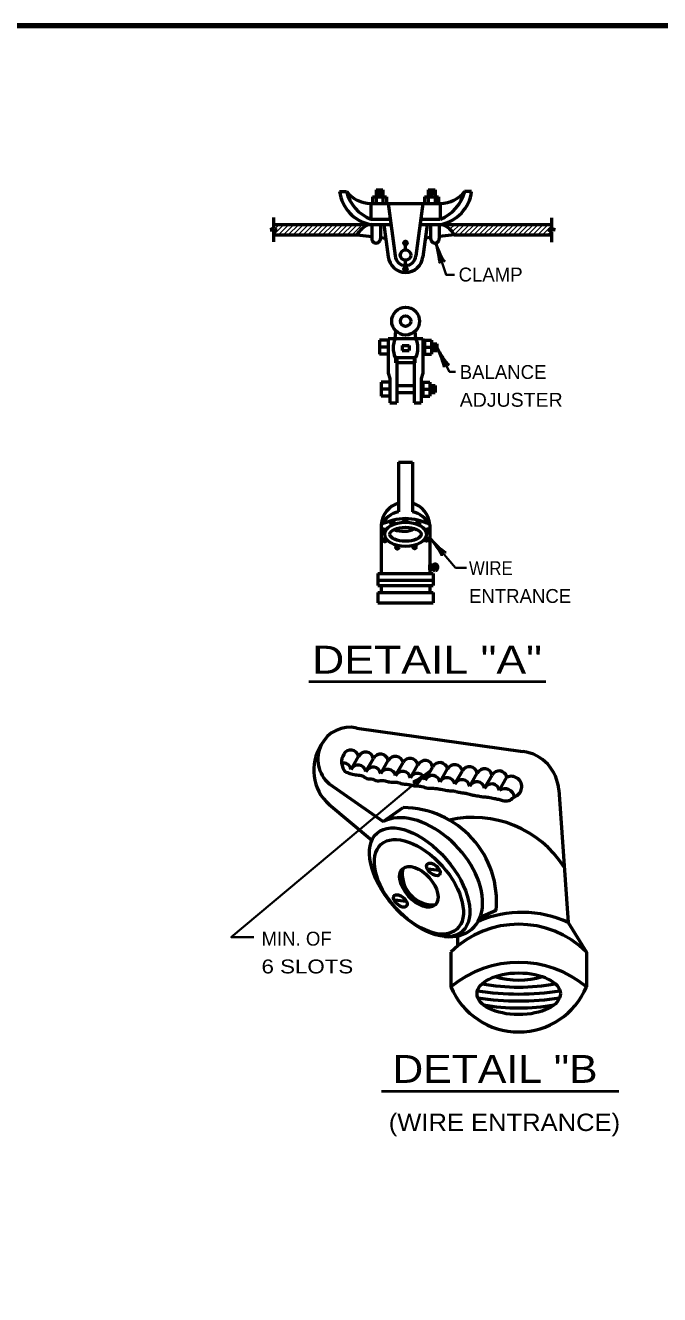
# Model space of a CAD drawing. Extents: x -370 to 486, y -203 to 341.
# Drawn here: x -153.5 to -43.9, y 115.9 to 334.9 of the extents above; entities that cross this region are included whole.
import ezdxf
from ezdxf.enums import TextEntityAlignment as Align

# ---------------------------------------------------------------- set-up
doc = ezdxf.new("R2010")
doc.units = 0
doc.header["$LTSCALE"] = 0.96
doc.layers.add('1', color=7, linetype='Continuous', lineweight=53)

msp = doc.modelspace()

# ---------------------------------------------------------------- hatches: boundary and pattern name
at = {"layer": '1'}
for points in [[(-87.5088, 249.4967, 1), (-88.1088, 249.4967, 1)], [(-91.2993, 247.743, 1), (-91.8993, 247.743, 1)], [(-89.7594, 249.0701, 1), (-90.3594, 249.0701, 1)], [(-85.2937, 249.0938, 1), (-85.8937, 249.0938, 1)], [(-83.7302, 247.743, 1), (-84.3302, 247.743, 1)], [(-91.086, 246.096, 1), (-91.686, 246.096, 1)], [(-83.8723, 246.1908, 1), (-84.4723, 246.1908, 1)], [(-88.9065, 244.84, 1), (-89.5065, 244.84, 1)], [(-85.9215, 244.8993, 1), (-86.5215, 244.8993, 1)]]:
    msp.add_hatch(color=256, dxfattribs=at).paths.add_polyline_path(points)
h = msp.add_hatch(color=256, dxfattribs=at)
edge = h.paths.add_edge_path()
edge.add_ellipse((-82.7123, 241.4022), major_axis=(0, -0.6), ratio=0.75, start_angle=0, end_angle=360)

# ---------------------------------------------------------------- linework, layer by layer
for p, q in [((-99.2043, 306.2737), (-98.0043, 306.2737)), ((-93.5043, 305.3737), (-91.1044, 305.3737)), ((-93.5043, 305.3737), (-93.5043, 304.1737)), ((-92.9043, 306.5737), (-92.9043, 304.1737)), ((-92.9043, 306.5737), (-91.7044, 306.5737)), ((-92.9043, 305.9737), (-91.7044, 305.9737)), ((-92.6043, 306.2737), (-92.0044, 306.2737)), ((-92.6043, 305.6737), (-92.0044, 305.6737)), ((-91.7044, 306.5737), (-91.7044, 304.1737)), ((-91.1044, 305.3737), (-91.1044, 304.1737)), ((-84.5042, 305.3737), (-82.1043, 305.3737)), ((-84.5042, 305.3737), (-84.5042, 304.1737)), ((-83.9042, 306.5737), (-83.9042, 304.1737)), ((-83.9042, 306.5737), (-82.7043, 306.5737)), ((-83.9042, 305.9737), (-82.7043, 305.9737)), ((-83.6042, 306.2737), (-83.0043, 306.2737)), ((-83.6042, 305.6737), (-83.0043, 305.6737)), ((-82.7043, 306.5737), (-82.7043, 304.1737)), ((-82.1043, 305.3737), (-82.1043, 304.1737)), ((-76.4043, 306.2737), (-77.6043, 306.2737)), ((-93.8043, 304.1737), (-93.8043, 301.4737)), ((-90.8044, 304.1737), (-89.6043, 295.1727)), ((-84.8042, 304.1737), (-86.0043, 295.1727)), ((-81.8043, 304.1737), (-81.8043, 301.4737)), ((-110.6043, 301.7737), (-110.6043, 299.9737)), ((-110.6043, 300.5737), (-93.8043, 300.5737)), ((-93.6351, 300.5737), (-94.2328, 300.5214)), ((-93.8043, 301.4737), (-90.4444, 301.4737)), ((-93.8043, 300.5737), (-90.3244, 300.5737)), ((-93.6351, 300.5737), (-93.6351, 298.1737)), ((-92.1351, 300.5737), (-92.1351, 298.1737)), ((-91.5351, 300.5737), (-90.7938, 295.0142)), ((-85.2842, 300.5737), (-81.8043, 300.5737)), ((-85.1642, 301.4737), (-81.8043, 301.4737)), ((-84.0738, 300.5737), (-84.8149, 295.0142)), ((-83.4738, 300.5737), (-83.4738, 298.1737)), ((-81.9738, 300.5737), (-81.9738, 298.1737)), ((-81.9697, 300.5737), (-81.372, 300.5214)), ((-81.8043, 300.5737), (-62.6043, 300.5737)), ((-62.5683, 301.7295), (-62.5683, 299.9295)), ((-110.6043, 299.9737), (-111.2043, 299.6737)), ((-111.2043, 299.6737), (-110.0043, 299.6737)), ((-110.0043, 299.6737), (-110.6043, 299.3737)), ((-110.6043, 299.3737), (-110.6043, 297.5737)), ((-110.6043, 298.7737), (-96.2043, 298.7737)), ((-96.2043, 298.7737), (-93.6351, 298.4754)), ((-92.1351, 298.3013), (-91.2179, 298.1948)), ((-83.4738, 298.3012), (-84.3909, 298.1948)), ((-79.4043, 298.7737), (-81.9738, 298.4754)), ((-79.4043, 298.7737), (-62.6043, 298.7737)), ((-61.9683, 299.6295), (-63.1683, 299.6295)), ((-63.1683, 299.6295), (-62.5683, 299.3295)), ((-62.5683, 299.9295), (-61.9683, 299.6295)), ((-62.5683, 299.3295), (-62.5683, 297.5295)), ((-87.8043, 296.1949), (-87.8043, 297.0805)), ((-87.8043, 293.1956), (-87.8043, 294.3949)), ((-90.8043, 280.5938), (-92.3043, 280.5938)), ((-92.3043, 280.5938), (-92.3043, 278.1938)), ((-90.8043, 280.8938), (-84.8043, 280.8938)), ((-90.8043, 280.8938), (-90.8043, 274.8938)), ((-89.6043, 280.8938), (-89.491, 282.1892)), ((-86.0043, 280.8938), (-86.1167, 282.1779)), ((-84.8043, 280.8938), (-84.8043, 274.8938)), ((-84.8043, 280.5938), (-83.3043, 280.5938)), ((-84.5043, 280.5938), (-84.5043, 278.1938)), ((-83.3043, 280.5938), (-83.3043, 278.1938)), ((-90.8043, 279.3938), (-92.3043, 279.3938)), ((-88.4043, 279.6938), (-87.2043, 279.6938)), ((-88.4043, 279.6938), (-88.4043, 278.7938)), ((-88.4043, 278.7938), (-87.2043, 278.7938)), ((-87.2043, 279.6938), (-87.2043, 278.7938)), ((-84.5043, 279.3938), (-83.3043, 279.3938)), ((-83.3043, 279.9938), (-82.4043, 279.9938)), ((-83.3043, 278.7938), (-82.4043, 278.7938)), ((-83.0793, 279.6938), (-83.0793, 279.0938)), ((-82.8543, 279.9938), (-82.8543, 278.7938)), ((-82.6293, 279.6938), (-82.6293, 279.0938)), ((-82.4043, 279.9938), (-82.4043, 278.7938)), ((-90.8043, 278.1938), (-92.3043, 278.1938)), ((-89.6043, 277.5938), (-86.0043, 277.5938)), ((-89.4543, 276.6938), (-89.4543, 277.5938)), ((-89.4543, 276.7655), (-86.1543, 276.7655)), ((-89.3919, 276.6938), (-89.3919, 277.5938)), ((-89.3919, 276.6938), (-89.3919, 277.5938)), ((-89.3644, 276.6938), (-89.3644, 277.5938)), ((-89.3644, 276.6938), (-89.3644, 277.5938)), ((-89.3095, 276.6938), (-89.3095, 277.5938)), ((-89.3043, 277.5938), (-89.3043, 269.7938)), ((-86.3043, 277.5938), (-86.3043, 269.7938)), ((-86.2472, 276.6938), (-86.2472, 277.5938)), ((-86.2334, 276.6938), (-86.2334, 277.5938)), ((-86.206, 276.6938), (-86.206, 277.5938)), ((-86.1922, 276.6938), (-86.1922, 277.5938)), ((-86.1785, 276.6938), (-86.1785, 277.5938)), ((-86.1543, 276.6938), (-86.1543, 277.5938)), ((-84.8043, 278.1938), (-83.3043, 278.1938)), ((-90.8043, 274.8938), (-90.5043, 273.9938)), ((-90.5043, 273.9938), (-90.5043, 269.7938)), ((-84.8043, 274.8938), (-85.1043, 273.9938)), ((-85.1043, 273.9938), (-85.1043, 269.7938)), ((-90.5387, 273.3522), (-92.0387, 273.3522)), ((-92.0387, 273.3522), (-92.0387, 270.9522)), ((-90.5387, 272.1522), (-92.0387, 272.1522)), ((-89.3043, 272.7522), (-86.3043, 272.7522)), ((-85.1043, 273.3522), (-83.6043, 273.3522)), ((-84.8043, 273.3522), (-84.8043, 270.9522)), ((-84.8043, 272.1522), (-83.6043, 272.1522)), ((-83.6043, 273.3522), (-83.6043, 270.9522)), ((-83.6043, 272.7522), (-82.7043, 272.7522)), ((-83.3793, 272.4522), (-83.3793, 271.8522)), ((-83.1543, 272.7522), (-83.1543, 271.5522)), ((-82.9293, 272.4522), (-82.9293, 271.8522)), ((-82.7043, 272.7522), (-82.7043, 271.5522)), ((-90.5387, 270.9522), (-92.0387, 270.9522)), ((-90.5043, 269.7938), (-89.3043, 269.7938)), ((-89.3043, 271.5522), (-86.3043, 271.5522)), ((-86.3043, 269.7938), (-85.1043, 269.7938)), ((-85.1043, 270.9522), (-83.6043, 270.9522)), ((-83.6043, 271.5522), (-82.7043, 271.5522)), ((-89.0043, 259.5522), (-86.6043, 259.5522)), ((-89.0043, 259.5522), (-89.0043, 251.0022)), ((-86.6043, 259.5522), (-86.6043, 251.0022)), ((-92.0043, 248.7522), (-92.0043, 240.3522)), ((-83.6043, 248.7522), (-83.6043, 241.8522)), ((-92.6043, 240.3522), (-83.0043, 240.3522)), ((-92.6043, 240.3522), (-92.6043, 238.2522)), ((-92.6043, 239.1522), (-83.0043, 239.1522)), ((-83.6043, 240.9522), (-83.6043, 240.3522)), ((-83.0043, 240.3522), (-83.0043, 238.2522)), ((-92.6043, 238.2522), (-83.0043, 238.2522)), ((-92.6043, 237.0522), (-83.0043, 237.0522)), ((-92.6043, 237.0522), (-92.6043, 235.2522)), ((-92.0043, 238.2522), (-92.0043, 237.0522)), ((-83.6043, 238.2522), (-83.6043, 237.0522)), ((-83.0043, 237.0522), (-83.0043, 235.2522)), ((-92.6043, 235.2522), (-83.0043, 235.2522)), ((-96.2043, 213.6522), (-67.5168, 209.6205)), ((-97.2065, 206.5224), (-95.9123, 208.7641)), ((-94.6433, 206.1622), (-93.3491, 208.4038)), ((-92.08, 205.8019), (-90.7858, 208.0436)), ((-89.5167, 205.4417), (-88.2225, 207.6834)), ((-86.9535, 205.0815), (-85.6594, 207.3231)), ((-84.3902, 204.7212), (-83.096, 206.9629)), ((-81.8269, 204.361), (-80.5327, 206.6026)), ((-79.2637, 204.0007), (-77.9695, 206.2424)), ((-101.0043, 204.0522), (-91.666, 197.5134)), ((-76.7004, 203.6405), (-75.4062, 205.8822)), ((-74.1371, 203.2803), (-72.8429, 205.5219)), ((-71.5739, 202.92), (-70.2796, 205.1617)), ((-61.3364, 202.9927), (-59.734, 180.0792)), ((-101.0043, 200.4522), (-93.6503, 194.2814)), ((-91.666, 197.5134), (-88.2256, 199.9224)), ((-83.9561, 189.3303), (-82.005, 189.1294)), ((-89.6946, 183.9917), (-87.7148, 183.7908)), ((-72.1429, 182.1709), (-74.9313, 180.9801)), ((-78.7546, 176.0669), (-78.7546, 177.7848)), ((-79.9546, 174.9909), (-79.9546, 168.9909))]:
    msp.add_line(p, q, dxfattribs=at)
at = {"layer": '1', "lineweight": 25}
for p, q in [((-110.6043, 298.7737), (-108.8043, 300.5737)), ((-110.5529, 299.6737), (-109.6529, 300.5737)), ((-109.7559, 298.7737), (-107.9559, 300.5737)), ((-108.9073, 298.7737), (-107.1073, 300.5737)), ((-108.0589, 298.7737), (-106.2589, 300.5737)), ((-107.2103, 298.7737), (-105.4103, 300.5737)), ((-106.3617, 298.7737), (-104.5617, 300.5737)), ((-105.5133, 298.7737), (-103.7133, 300.5737)), ((-104.6647, 298.7737), (-102.8647, 300.5737)), ((-103.8161, 298.7737), (-102.0161, 300.5737)), ((-102.9677, 298.7737), (-101.1677, 300.5737)), ((-102.1191, 298.7737), (-100.3191, 300.5737)), ((-101.2707, 298.7737), (-99.4707, 300.5737)), ((-100.4221, 298.7737), (-98.6221, 300.5737)), ((-99.5735, 298.7737), (-97.7735, 300.5737)), ((-98.7251, 298.7737), (-96.9251, 300.5737)), ((-97.8767, 298.7737), (-96.0767, 300.5737)), ((-97.0281, 298.7737), (-95.2281, 300.5737)), ((-80.6056, 300.1182), (-80.1501, 300.5737)), ((-80.1359, 299.7393), (-79.3015, 300.5737)), ((-79.7341, 299.2925), (-78.4529, 300.5737)), ((-79.4043, 298.7737), (-77.6043, 300.5737)), ((-78.5559, 298.7737), (-76.7559, 300.5737)), ((-77.7073, 298.7737), (-75.9073, 300.5737)), ((-76.8589, 298.7737), (-75.0589, 300.5737)), ((-76.0103, 298.7737), (-74.2103, 300.5737)), ((-75.1617, 298.7737), (-73.3617, 300.5737)), ((-74.3133, 298.7737), (-72.5133, 300.5737)), ((-73.4649, 298.7737), (-71.6649, 300.5737)), ((-72.6163, 298.7737), (-70.8163, 300.5737)), ((-71.7679, 298.7737), (-69.9679, 300.5737)), ((-70.9193, 298.7737), (-69.1193, 300.5737)), ((-70.0707, 298.7737), (-68.2707, 300.5737)), ((-69.2223, 298.7737), (-67.4223, 300.5737)), ((-68.3737, 298.7737), (-66.5737, 300.5737)), ((-67.5253, 298.7737), (-65.7253, 300.5737)), ((-66.6767, 298.7737), (-64.8767, 300.5737)), ((-65.8283, 298.7737), (-64.0283, 300.5737)), ((-64.9797, 298.7737), (-63.1797, 300.5737)), ((-64.1311, 298.7737), (-62.5683, 300.3365)), ((-63.2827, 298.7737), (-62.674, 299.3824))]:
    msp.add_line(p, q, dxfattribs=at)
at = {"layer": '1', "lineweight": 40}
for p, q in [((-104.5149, 221.6891), (-63.5509, 221.6891)), ((-91.9537, 150.9917), (-50.9897, 150.9917))]:
    msp.add_line(p, q, dxfattribs=at)
at = {"layer": '1', "lineweight": 158}
msp.add_lwpolyline([(479.406, 334.9398), (-312.294, 334.8398), (-312.194, -191.1602)], dxfattribs=at)
at = {"layer": '1'}
for points in [[(-93.8043, 304.1737), (-90.8044, 304.1737), (-84.8042, 304.1737), (-81.8043, 304.1737)], [(-59.7341, 180.0792), (-56.5546, 174.9909), (-56.5546, 168.9909)]]:
    msp.add_lwpolyline(points, dxfattribs=at)
at = {"layer": '1', "lineweight": 35}
for points in [[(-82.5442, 297.3097), (-80.7948, 291.8891), (-79.3707, 291.8891)], [(-82.2882, 279.2127), (-80.1975, 275.1153), (-79.1584, 275.1153)], [(-83.4318, 246.3099), (-79.1493, 241.3198), (-77.2662, 241.3198)], [(-83.589, 206.2782), (-117.8957, 177.5452), (-114.0022, 177.5452)]]:
    msp.add_lwpolyline(points, dxfattribs=at)
at = {"layer": '1'}
msp.add_lwpolyline([(-83.6043, 240.9522), (-83.6043, 241.8522), (-83.0043, 241.8522), (-83.0043, 240.9522)], close=True, dxfattribs=at)
for centre, radius in [((-87.8035, 295.2949), 0.9), ((-87.8096, 297.3805), 0.3), ((-87.8096, 292.8956), 0.3), ((-87.7981, 283.8904), 2.4), ((-87.7981, 283.8904), 0.9), ((-87.8088, 249.4967), 0.3), ((-91.5993, 247.743), 0.3), ((-90.0594, 249.0701), 0.3), ((-85.5937, 249.0938), 0.3), ((-84.0302, 247.743), 0.3), ((-91.386, 246.096), 0.3), ((-84.1723, 246.1908), 0.3), ((-89.2065, 244.84), 0.3), ((-86.2215, 244.8993), 0.3)]:
    msp.add_circle(centre, radius, dxfattribs=at)
for centre, radius, start, end in [((-92.5532, 307.1668), 6.7108, 187.64817, 259.25551), ((-93.6032, 309.8259), 5.6557, 218.90739, 267.9625), ((-91.1949, 307.9944), 7.0235, 194.18169, 248.19017), ((-83.0342, 307.1668), 6.7108, 280.74449, 352.35183), ((-81.9842, 309.8259), 5.6557, 272.0375, 321.09261), ((-84.3925, 307.9944), 7.0235, 291.80983, 345.81831), ((-92.5815, 296.6729), 4.1878, 113.22226, 149.89059), ((-82.7378, 296.9949), 3.7817, 28.05788, 68.82928), ((-92.8851, 298.1225), 0.7517, 176.096, 3.904), ((-82.7238, 298.1225), 0.7517, 176.096, 3.904), ((-87.8043, 295.2966), 3.0027, 185.3956, 354.6044), ((-87.8043, 295.2982), 1.8044, 183.98846, 356.01154), ((-85.6711, 279.2438), 4.2653, 157.24187, 202.75812), ((-89.8059, 279.2438), 4.1442, 336.53763, 23.46238), ((-87.8043, 248.4407), 4.2115, 106.55476, 175.75781), ((-87.8043, 248.4407), 4.2115, 4.24219, 73.44524), ((-87.8043, 246.2772), 4.875, 104.25003, 149.48976), ((-87.8043, 240.8772), 8.925, 61.92751, 118.07249), ((-87.8043, 246.2772), 4.875, 30.51024, 75.74997), ((-88.1945, 252.1368), 4.5203, 249.21209, 295.95947), ((-97.4161, 208.2581), 5.5285, 77.33852, 229.53137), ((-95.7386, 206.3759), 7.9258, 146.67294, 228.36581), ((-96.2685, 207.7939), 2.5771, 148.91645, 220.4444), ((-97.2586, 208.4841), 1.3751, 11.75001, 152.2471), ((-94.6954, 208.1238), 1.3751, 11.75001, 152.2471), ((-92.1322, 207.7635), 1.3751, 11.75001, 152.2471), ((-89.5689, 207.4033), 1.3751, 11.75001, 152.2471), ((-87.0056, 207.0431), 1.3751, 11.75001, 152.2471), ((-68.5189, 202.4906), 7.2, 3.99951, 81.99965), ((-98.5528, 206.2424), 1.3751, 11.75001, 101.93956), ((-95.9896, 205.8821), 1.3751, 11.75001, 152.2471), ((-93.4264, 205.5219), 1.3751, 11.75001, 152.2471), ((-90.8631, 205.1616), 1.3751, 11.75001, 152.2471), ((-88.2998, 204.8014), 1.3751, 11.75001, 152.2471), ((-84.4425, 206.6828), 1.3751, 11.75001, 152.2471), ((-81.8791, 206.3226), 1.3751, 11.75001, 152.2471), ((-79.3158, 205.9623), 1.3751, 11.75001, 152.2471), ((-76.7526, 205.6021), 1.3751, 11.75001, 152.2471), ((-74.1893, 205.2419), 1.3751, 11.75001, 152.2471), ((-71.626, 204.8816), 1.3751, 11.75001, 152.2471), ((-85.7366, 204.4412), 1.3751, 11.75001, 152.2471), ((-83.1733, 204.0809), 1.3751, 11.75001, 152.2471), ((-80.61, 203.7207), 1.3751, 11.75001, 152.2471), ((-78.0468, 203.3604), 1.3751, 11.75001, 152.2471), ((-75.4835, 203.0002), 1.3751, 11.75001, 152.2471), ((-72.9202, 202.64), 1.3751, 11.75001, 152.2471), ((-69.5297, 203.5227), 1.8024, 287.78042, 114.58588), ((-70.6825, 201.4176), 1.747, 12.8606, 120.68146), ((-88.321, 183.6748), 16.2478, 354.68901, 89.66358), ((-76.1328, 179.5376), 18.7024, 32.75237, 102.73689), ((-82.9767, 188.5003), 5.393, 170.61826, 272.91325), ((-67.7217, 162.906), 18.9399, 65.05583, 113.43858), ((-68.2546, 163.1315), 16.6594, 45.38759, 134.61241), ((-68.2546, 154.7945), 18.3964, 50.50632, 129.49367), ((-68.2546, 173.8659), 12.675, 202.61986, 337.38013), ((-68.2546, 204.5386), 35.5923, 259.76655, 280.23345), ((-68.2546, 184.532), 14.3857, 253.39383, 286.60618), ((-68.2546, 213.2961), 45.5498, 260.99995, 279.00005), ((-68.2546, 211.7823), 45.236, 261.0124, 278.9876), ((-68.2546, 199.6964), 34.3501, 259.73317, 280.26683)]:
    msp.add_arc(centre, radius, start, end, dxfattribs=at)
at = {"layer": '1', "lineweight": 40}
for centre, major_axis, ratio, start_param, end_param in [((-82.3729, 295.9521), (0.4468, -2.0706), 0.07063, 6.28230741, 8.55970261), ((-81.8265, 296.1654), (-0.8365, 1.9817), 0.122415, 0.89635335, 3.14159265), ((-81.9033, 277.8996), (0.7702, -1.9733), 0.07063, 6.28230741, 8.55970261), ((-81.3977, 278.197), (-1.1408, 1.8236), 0.122415, 0.89635335, 3.14159265), ((-82.7488, 245.1242), (1.2127, -1.7368), 0.07063, 6.28230741, 8.55970261), ((-82.3274, 245.5321), (-1.5377, 1.5041), 0.122415, 0.89635335, 3.14159265), ((-84.7829, 205.6095), (-1.7512, -1.1918), 0.07063, 6.28230741, 8.55970261), ((-84.38, 205.1832), (1.5225, 1.5195), 0.122415, 0.89635335, 3.14159265)]:
    msp.add_ellipse(centre, major_axis=major_axis, ratio=ratio, start_param=start_param, end_param=end_param, dxfattribs=at)
at = {"layer": '1'}
for centre, major_axis, ratio in [((-87.8043, 247.1022), (-3.6, 0), 0.583333), ((-87.8043, 247.1022), (-2.7, 0), 0.444444), ((-82.7123, 241.4022), (0, -0.6), 0.75), ((-85.3693, 187.0394), (7.3469, -8.4941), 0.541131), ((-85.5001, 186.2468), (6.5505, -7.3352), 0.549098), ((-85.5001, 186.2468), (2.7975, -3.1326), 0.571425), ((-82.9948, 189.2442), (1.0473, -0.9185), 0.559667), ((-88.7047, 183.8195), (1.0473, -0.9185), 0.559667), ((-68.2546, 167.7909), (7.2, 0), 0.5)]:
    msp.add_ellipse(centre, major_axis=major_axis, ratio=ratio, dxfattribs=at)
msp.add_ellipse((-84.4857, 187.9043), major_axis=(8.2992, -8.8184), ratio=0.63331, start_param=5.65532628, end_param=9.24694428, dxfattribs=at)
msp.add_spline([(-98.2409, 206.1263), (-97.4109, 205.8173), (-96.4632, 205.5985), (-95.9164, 205.5256), (-95.1145, 205.3433), (-94.9322, 205.1974), (-93.9845, 204.8692), (-93.7294, 204.8692), (-92.6723, 204.5411), (-92.1984, 204.5775), (-91.3236, 204.5411), (-90.5581, 204.3588), (-90.0478, 204.3223), (-89.4646, 204.3223), (-88.845, 204.1765), (-88.3711, 204.0306), (-88.0066, 203.9941), (-87.1682, 203.8848), (-86.6579, 203.7754), (-85.9653, 203.666), (-85.2363, 203.6295), (-84.2157, 203.3378), (-84.0334, 203.3014), (-83.7054, 203.3014), (-83.1222, 203.2649), (-82.3567, 203.192), (-81.7006, 203.0826), (-80.6071, 202.9003), (-80.1332, 202.8273), (-79.2948, 202.7544), (-79.0397, 202.6815), (-78.6752, 202.6086), (-78.0191, 202.4992), (-77.3994, 202.3898), (-76.561, 202.171), (-75.7591, 202.0252), (-74.7749, 201.8428), (-74.0824, 201.7699), (-73.4627, 201.697), (-72.4785, 201.5147), (-72.1505, 201.4418), (-71.385, 201.2594), (-70.7654, 201.1136), (-70.255, 201.1136), (-69.8905, 201.1501), (-69.3073, 201.5511), (-68.7798, 201.8837)], degree=3, dxfattribs=at)

# ---------------------------------------------------------------- texts
msp.add_text('CLAMP', height=2.4, dxfattribs=at).set_placement((-73.1146, 290.7318), align=Align.CENTER)
for s, p in [('BALANCE', (-78.4481, 273.9104)), ('ENTRANCE', (-76.8433, 235.2496)), ('MIN. OF', (-112.6799, 176.1006))]:
    msp.add_text(s, height=2.4, dxfattribs=at).set_placement(p)
for s, width, p in [('ADJUSTER', 1.05, (-78.4481, 269.1104)), ('WIRE', 0.9, (-76.8433, 240.0496)), ('6 SLOTS', 1.2, (-112.6799, 171.3006))]:
    msp.add_text(s, height=2.4, dxfattribs=dict(at, width=width)).set_placement(p)
for s, height, width, p in [('DETAIL "A"', 4.8, 1.2, (-84.0907, 223.0552)), ('DETAIL "B', 4.8, 1.15, (-72.3578, 152.4104)), ('(WIRE ENTRANCE)', 3, 1.1, (-70.7236, 144.0994))]:
    msp.add_text(s, height=height, dxfattribs=dict(at, width=width)).set_placement(p, align=Align.CENTER)

doc.saveas('drawing.dxf')
